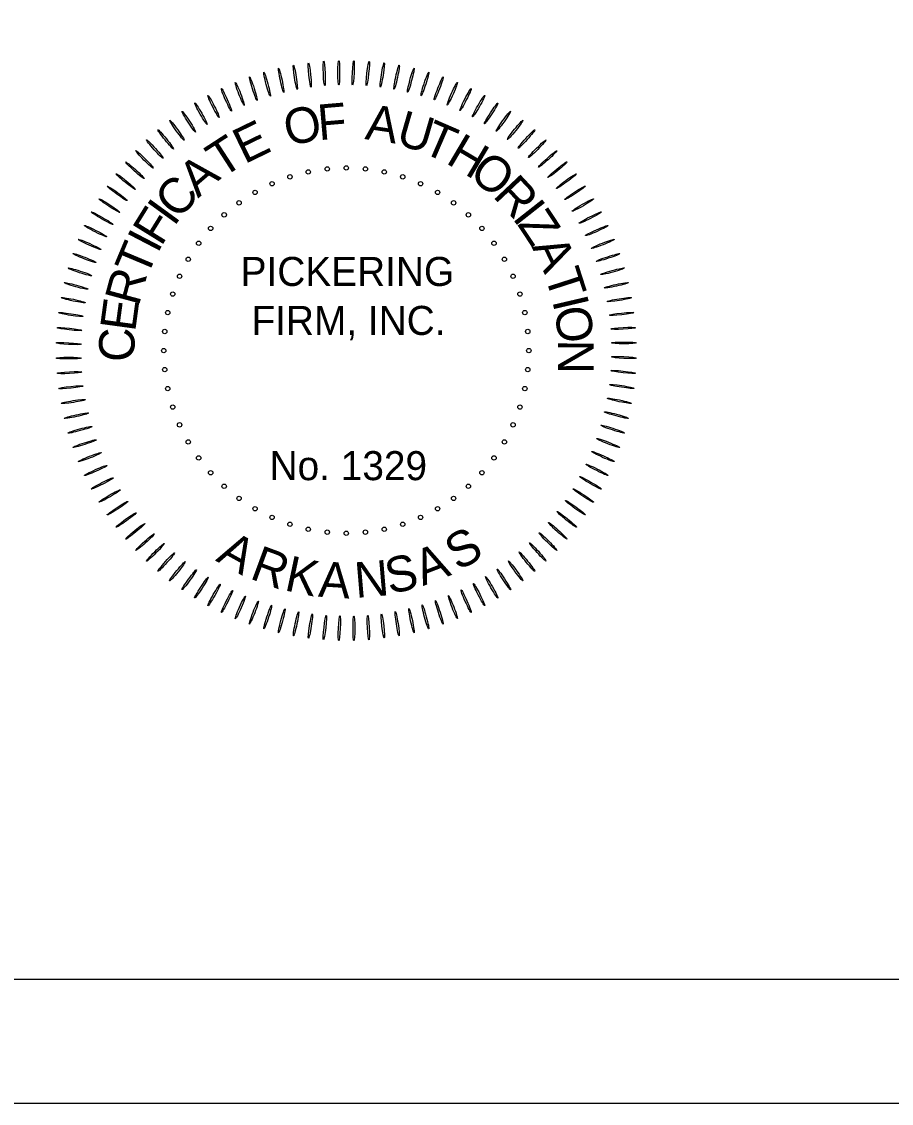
# Model space of a CAD drawing. Extents: x 1368042 to 1371376, y 380392 to 382637.
# Drawn here: x 1370746.8 to 1371026.4, y 380392 to 380739.5 of the extents above; entities that cross this region are included whole.
import ezdxf

# ---------------------------------------------------------------- set-up
doc = ezdxf.new("R2010")
doc.units = 0
for name, color, linetype in [('G-COA-ANNO', 7, 'Continuous'), ('G-COA-LINE', 7, 'Continuous'), ('R_Border', 7, 'Continuous'), ('R_No Plot', 7, 'Continuous'), ('STAMP_COA', 7, 'Continuous')]:
    doc.layers.add(name, color=color, linetype=linetype)

# ---------------------------------------------------------------- blocks, each defined once
blk = doc.blocks.new('Pickering-COA AR-ENG')
at = {"layer": 'G-COA-LINE'}
for centre in [(-0.427, 5.137), (-0.427, 5.137), (-0.228, 5.168), (-0.228, 5.168), (-0.028, 5.179), (-0.028, 5.179), (0.173, 5.168), (0.173, 5.168), (0.371, 5.137), (0.371, 5.137), (-0.808, 5.013), (-0.808, 5.013), (-0.62, 5.085), (-0.62, 5.085), (0.565, 5.085), (0.565, 5.085), (0.752, 5.013), (0.752, 5.013), (-0.987, 4.922), (-0.987, 4.922), (0.931, 4.922), (0.931, 4.922), (-1.155, 4.812), (-1.155, 4.812), (1.099, 4.812), (1.099, 4.812), (-1.311, 4.686), (-1.311, 4.686), (1.255, 4.686), (1.255, 4.686), (-1.453, 4.544), (-1.453, 4.544), (1.397, 4.544), (1.397, 4.544), (-1.579, 4.388), (-1.579, 4.388), (1.524, 4.388), (1.524, 4.388), (-1.689, 4.22), (-1.689, 4.22), (1.633, 4.22), (1.633, 4.22), (-1.78, 4.041), (-1.78, 4.041), (1.724, 4.041), (1.724, 4.041), (-1.852, 3.854), (-1.852, 3.854), (1.796, 3.854), (1.796, 3.854), (-1.904, 3.66), (-1.904, 3.66), (1.848, 3.66), (1.848, 3.66), (-1.935, 3.461), (-1.935, 3.461), (1.879, 3.461), (1.879, 3.461), (-1.946, 3.261), (-1.946, 3.261), (1.89, 3.261), (1.89, 3.261), (-1.935, 3.061), (-1.935, 3.061), (1.879, 3.061), (1.879, 3.061), (-1.904, 2.862), (-1.904, 2.862), (1.848, 2.862), (1.848, 2.862), (-1.852, 2.668), (-1.852, 2.668), (1.796, 2.668), (1.796, 2.668), (-1.78, 2.481), (-1.78, 2.481), (1.724, 2.481), (1.724, 2.481), (-1.689, 2.302), (-1.689, 2.302), (1.633, 2.302), (1.633, 2.302), (-1.579, 2.134), (-1.579, 2.134), (1.524, 2.134), (1.524, 2.134), (-1.453, 1.978), (-1.453, 1.978), (1.397, 1.978), (1.397, 1.978), (-1.311, 1.836), (-1.311, 1.836), (1.255, 1.836), (1.255, 1.836), (-1.155, 1.709), (-1.155, 1.709), (1.099, 1.709), (1.099, 1.709), (-0.987, 1.6), (-0.987, 1.6), (0.931, 1.6), (0.931, 1.6), (-0.808, 1.509), (-0.808, 1.509), (0.752, 1.509), (0.752, 1.509), (-0.62, 1.437), (-0.62, 1.437), (-0.427, 1.385), (-0.427, 1.385), (-0.228, 1.354), (-0.228, 1.354), (-0.028, 1.343), (-0.028, 1.343), (0.173, 1.354), (0.173, 1.354), (0.371, 1.385), (0.371, 1.385), (0.565, 1.437), (0.565, 1.437)]:
    blk.add_circle(centre, 0.0229, dxfattribs=at)
for centre, major_axis in [((-0.563, 6.13), (0.02, -0.128)), ((-0.563, 6.13), (0.02, -0.128)), ((-0.412, 6.154), (0.014, -0.129)), ((-0.412, 6.154), (0.014, -0.129)), ((-0.26, 6.17), (0.006, -0.13)), ((-0.26, 6.17), (0.006, -0.13)), ((-0.107, 6.178), (0, -0.13)), ((-0.107, 6.178), (0, -0.13)), ((0.045, 6.178), (-0.007, -0.13)), ((0.045, 6.178), (-0.007, -0.13)), ((0.198, 6.171), (-0.014, -0.129)), ((0.198, 6.171), (-0.014, -0.129)), ((0.35, 6.155), (-0.02, -0.128)), ((0.35, 6.155), (-0.02, -0.128)), ((0.501, 6.131), (-0.027, -0.127)), ((0.501, 6.131), (-0.027, -0.127)), ((-1.005, 6.011), (0.04, -0.124)), ((-1.005, 6.011), (0.04, -0.124)), ((-0.86, 6.058), (0.034, -0.126)), ((-0.86, 6.058), (0.034, -0.126)), ((-0.712, 6.098), (0.027, -0.127)), ((-0.712, 6.098), (0.027, -0.127)), ((0.65, 6.099), (-0.034, -0.126)), ((0.65, 6.099), (-0.034, -0.126)), ((0.798, 6.06), (-0.04, -0.124)), ((0.798, 6.06), (-0.04, -0.124)), ((0.943, 6.013), (-0.047, -0.121)), ((0.943, 6.013), (-0.047, -0.121)), ((-1.147, 5.956), (0.047, -0.121)), ((-1.147, 5.956), (0.047, -0.121)), ((1.086, 5.958), (-0.053, -0.119)), ((1.086, 5.958), (-0.053, -0.119)), ((-1.423, 5.824), (0.059, -0.116)), ((-1.423, 5.824), (0.059, -0.116)), ((-1.287, 5.894), (0.053, -0.119)), ((-1.287, 5.894), (0.053, -0.119)), ((1.225, 5.896), (-0.059, -0.116)), ((1.225, 5.896), (-0.059, -0.116)), ((1.362, 5.827), (-0.065, -0.113)), ((1.362, 5.827), (-0.065, -0.113)), ((-1.555, 5.748), (0.065, -0.113)), ((-1.555, 5.748), (0.065, -0.113)), ((1.494, 5.751), (-0.071, -0.109)), ((1.494, 5.751), (-0.071, -0.109)), ((-1.807, 5.574), (0.076, -0.105)), ((-1.807, 5.574), (0.076, -0.105)), ((-1.683, 5.664), (0.071, -0.109)), ((-1.683, 5.664), (0.071, -0.109)), ((1.622, 5.668), (-0.076, -0.105)), ((1.622, 5.668), (-0.076, -0.105)), ((1.746, 5.578), (-0.082, -0.101)), ((1.746, 5.578), (-0.082, -0.101)), ((-1.925, 5.478), (0.082, -0.101)), ((-1.925, 5.478), (0.082, -0.101)), ((1.865, 5.482), (-0.087, -0.0967)), ((1.865, 5.482), (-0.087, -0.0967)), ((-2.039, 5.376), (0.087, -0.0967)), ((-2.039, 5.376), (0.087, -0.0967)), ((1.978, 5.38), (-0.092, -0.092)), ((1.978, 5.38), (-0.092, -0.092)), ((-2.147, 5.268), (0.092, -0.092)), ((-2.147, 5.268), (0.092, -0.092)), ((2.087, 5.272), (-0.0967, -0.087)), ((2.087, 5.272), (-0.0967, -0.087)), ((-2.249, 5.154), (0.0967, -0.087)), ((-2.249, 5.154), (0.0967, -0.087)), ((2.189, 5.159), (-0.101, -0.082)), ((2.189, 5.159), (-0.101, -0.082)), ((-2.345, 5.035), (0.101, -0.082)), ((-2.345, 5.035), (0.101, -0.082)), ((2.285, 5.04), (-0.105, -0.076)), ((2.285, 5.04), (-0.105, -0.076)), ((-2.434, 4.911), (0.105, -0.076)), ((-2.434, 4.911), (0.105, -0.076)), ((2.375, 4.917), (-0.109, -0.071)), ((2.375, 4.917), (-0.109, -0.071)), ((-2.517, 4.783), (0.109, -0.071)), ((-2.517, 4.783), (0.109, -0.071)), ((2.458, 4.789), (-0.113, -0.065)), ((2.458, 4.789), (-0.113, -0.065)), ((-2.594, 4.651), (0.113, -0.065)), ((-2.594, 4.651), (0.113, -0.065)), ((2.535, 4.657), (-0.116, -0.059)), ((2.535, 4.657), (-0.116, -0.059)), ((-2.663, 4.515), (0.116, -0.059)), ((-2.663, 4.515), (0.116, -0.059)), ((2.604, 4.521), (-0.119, -0.053)), ((2.604, 4.521), (-0.119, -0.053)), ((-2.725, 4.375), (0.119, -0.053)), ((-2.725, 4.375), (0.119, -0.053)), ((2.667, 4.381), (-0.121, -0.047)), ((2.667, 4.381), (-0.121, -0.047)), ((-2.779, 4.232), (0.121, -0.047)), ((-2.779, 4.232), (0.121, -0.047)), ((2.722, 4.238), (-0.124, -0.04)), ((2.722, 4.238), (-0.124, -0.04)), ((-2.827, 4.087), (0.124, -0.04)), ((-2.827, 4.087), (0.124, -0.04)), ((2.769, 4.093), (-0.126, -0.034)), ((2.769, 4.093), (-0.126, -0.034)), ((-2.866, 3.939), (0.126, -0.034)), ((-2.866, 3.939), (0.126, -0.034)), ((2.809, 3.946), (-0.127, -0.027)), ((2.809, 3.946), (-0.127, -0.027)), ((-2.897, 3.79), (0.127, -0.027)), ((-2.897, 3.79), (0.127, -0.027)), ((2.841, 3.796), (-0.128, -0.02)), ((2.841, 3.796), (-0.128, -0.02)), ((-2.921, 3.639), (0.128, -0.02)), ((-2.921, 3.639), (0.128, -0.02)), ((2.865, 3.646), (-0.129, -0.013)), ((2.865, 3.646), (-0.129, -0.013)), ((-2.937, 3.487), (0.129, -0.014)), ((-2.937, 3.487), (0.129, -0.014)), ((2.881, 3.494), (-0.13, -0.007)), ((2.881, 3.494), (-0.13, -0.007)), ((-2.945, 3.334), (0.13, -0.007)), ((-2.945, 3.334), (0.13, -0.007)), ((2.889, 3.341), (-0.13, 0)), ((2.889, 3.341), (-0.13, 0)), ((-2.945, 3.182), (0.13, 0)), ((-2.945, 3.182), (0.13, 0)), ((2.889, 3.188), (-0.13, 0.006)), ((2.889, 3.188), (-0.13, 0.006)), ((-2.936, 3.029), (0.13, 0.007)), ((-2.936, 3.029), (0.13, 0.007)), ((2.881, 3.036), (-0.129, 0.014)), ((2.881, 3.036), (-0.129, 0.014)), ((-2.92, 2.876), (0.129, 0.013)), ((-2.92, 2.876), (0.129, 0.013)), ((2.866, 2.884), (-0.128, 0.02)), ((2.866, 2.884), (-0.128, 0.02)), ((-2.896, 2.726), (0.128, 0.02)), ((-2.896, 2.726), (0.128, 0.02)), ((2.842, 2.733), (-0.127, 0.027)), ((2.842, 2.733), (-0.127, 0.027)), ((2.81, 2.583), (-0.126, 0.034)), ((2.81, 2.583), (-0.126, 0.034)), ((-2.864, 2.577), (0.127, 0.027)), ((-2.864, 2.577), (0.127, 0.027)), ((-2.825, 2.429), (0.126, 0.034)), ((-2.825, 2.429), (0.126, 0.034)), ((2.771, 2.436), (-0.124, 0.04)), ((2.771, 2.436), (-0.124, 0.04)), ((-2.777, 2.284), (0.124, 0.04)), ((-2.777, 2.284), (0.124, 0.04)), ((2.724, 2.29), (-0.121, 0.047)), ((2.724, 2.29), (-0.121, 0.047)), ((-2.722, 2.142), (0.121, 0.047)), ((-2.722, 2.142), (0.121, 0.047)), ((2.669, 2.148), (-0.119, 0.053)), ((2.669, 2.148), (-0.119, 0.053)), ((-2.66, 2.002), (0.119, 0.053)), ((-2.66, 2.002), (0.119, 0.053)), ((2.607, 2.008), (-0.116, 0.059)), ((2.607, 2.008), (-0.116, 0.059)), ((2.538, 1.872), (-0.113, 0.065)), ((2.538, 1.872), (-0.113, 0.065)), ((-2.591, 1.866), (0.116, 0.059)), ((-2.591, 1.866), (0.116, 0.059)), ((-2.514, 1.734), (0.113, 0.065)), ((-2.514, 1.734), (0.113, 0.065)), ((2.462, 1.739), (-0.109, 0.071)), ((2.462, 1.739), (-0.109, 0.071)), ((-2.431, 1.606), (0.109, 0.071)), ((-2.431, 1.606), (0.109, 0.071)), ((2.379, 1.611), (-0.105, 0.076)), ((2.379, 1.611), (-0.105, 0.076)), ((-2.341, 1.482), (0.105, 0.076)), ((-2.341, 1.482), (0.105, 0.076)), ((2.289, 1.488), (-0.101, 0.082)), ((2.289, 1.488), (-0.101, 0.082)), ((-2.244, 1.364), (0.101, 0.082)), ((-2.244, 1.364), (0.101, 0.082)), ((2.193, 1.369), (-0.0967, 0.087)), ((2.193, 1.369), (-0.0967, 0.087)), ((-2.142, 1.25), (0.0967, 0.087)), ((-2.142, 1.25), (0.0967, 0.087)), ((2.091, 1.255), (-0.092, 0.092)), ((2.091, 1.255), (-0.092, 0.092)), ((-2.034, 1.142), (0.092, 0.092)), ((-2.034, 1.142), (0.092, 0.092)), ((-1.92, 1.04), (0.087, 0.0967)), ((-1.92, 1.04), (0.087, 0.0967)), ((1.87, 1.045), (-0.082, 0.101)), ((1.87, 1.045), (-0.082, 0.101)), ((1.983, 1.147), (-0.087, 0.0967)), ((1.983, 1.147), (-0.087, 0.0967)), ((-1.802, 0.944), (0.082, 0.101)), ((-1.802, 0.944), (0.082, 0.101)), ((1.751, 0.948), (-0.076, 0.105)), ((1.751, 0.948), (-0.076, 0.105)), ((-1.678, 0.855), (0.076, 0.105)), ((-1.678, 0.855), (0.076, 0.105)), ((1.628, 0.858), (-0.071, 0.109)), ((1.628, 0.858), (-0.071, 0.109)), ((-1.55, 0.772), (0.071, 0.109)), ((-1.55, 0.772), (0.071, 0.109)), ((-1.417, 0.695), (0.065, 0.113)), ((-1.417, 0.695), (0.065, 0.113)), ((1.367, 0.699), (-0.059, 0.116)), ((1.367, 0.699), (-0.059, 0.116)), ((1.5, 0.775), (-0.065, 0.113)), ((1.5, 0.775), (-0.065, 0.113)), ((-1.281, 0.626), (0.059, 0.116)), ((-1.281, 0.626), (0.059, 0.116)), ((-1.141, 0.564), (0.053, 0.119)), ((-1.141, 0.564), (0.053, 0.119)), ((1.092, 0.567), (-0.047, 0.121)), ((1.092, 0.567), (-0.047, 0.121)), ((1.231, 0.629), (-0.053, 0.119)), ((1.231, 0.629), (-0.053, 0.119)), ((-0.999, 0.51), (0.047, 0.121)), ((-0.999, 0.51), (0.047, 0.121)), ((-0.853, 0.463), (0.04, 0.124)), ((-0.853, 0.463), (0.04, 0.124)), ((0.804, 0.464), (-0.034, 0.126)), ((0.804, 0.464), (-0.034, 0.126)), ((0.949, 0.512), (-0.04, 0.124)), ((0.949, 0.512), (-0.04, 0.124)), ((-0.706, 0.423), (0.034, 0.126)), ((-0.706, 0.423), (0.034, 0.126)), ((-0.556, 0.392), (0.027, 0.127)), ((-0.556, 0.392), (0.027, 0.127)), ((-0.405, 0.368), (0.02, 0.128)), ((-0.405, 0.368), (0.02, 0.128)), ((-0.253, 0.352), (0.014, 0.129)), ((-0.253, 0.352), (0.014, 0.129)), ((-0.101, 0.344), (0.007, 0.13)), ((-0.101, 0.344), (0.007, 0.13)), ((0.052, 0.344), (0, 0.13)), ((0.052, 0.344), (0, 0.13)), ((0.204, 0.353), (-0.007, 0.13)), ((0.204, 0.353), (-0.007, 0.13)), ((0.356, 0.369), (-0.014, 0.129)), ((0.356, 0.369), (-0.014, 0.129)), ((0.507, 0.393), (-0.02, 0.128)), ((0.507, 0.393), (-0.02, 0.128)), ((0.657, 0.425), (-0.027, 0.127)), ((0.657, 0.425), (-0.027, 0.127))]:
    blk.add_ellipse(centre, major_axis=major_axis, ratio=0.070301, dxfattribs=at)
at = {"layer": 'G-COA-ANNO'}
for s, rotation, p in [('O', 12.2619, (-0.64, 5.405)), ('F', 4.8299, (-0.315, 5.469)), ('A', 351.5891, (0.16, 5.482)), ('E', 25.8553, (-1.098, 5.215)), ('U', 343.8069, (0.48, 5.43)), ('T', 336.5727, (0.748, 5.349)), ('T', 32.9353, (-1.337, 5.064)), ('H', 329.3464, (1.006, 5.235)), ('A', 40.7411, (-1.586, 4.856)), ('O', 321.4937, (1.246, 5.091)), ('C', 48.8967, (-1.791, 4.624)), ('R', 313.2703, (1.502, 4.882)), ('F', 58.2456, (-1.973, 4.346)), ('I', 53.972, (-1.839, 4.554)), ('I', 308.2054, (1.708, 4.653)), ('Z', 303.4877, (1.763, 4.587)), ('I', 62.5192, (-2.011, 4.27)), ('T', 67.2448, (-2.125, 4.013)), ('A', 295.6897, (1.917, 4.351)), ('R', 74.8418, (-2.21, 3.716)), ('T', 287.884, (2.053, 4.057)), ('E', 82.2613, (-2.247, 3.45)), ('I', 283.1584, (2.134, 3.787)), ('O', 277.8065, (2.157, 3.704)), ('C', 89.6911, (-2.253, 3.141)), ('N', 269.9408, (2.197, 3.376)), ('S', 29.451, (1.146, 0.941)), ('A', 331.0076, (-1.409, 1.057)), ('R', 339.6665, (-1.054, 0.871)), ('A', 21.072, (0.776, 0.787)), ('K', 347.9673, (-0.69, 0.746)), ('A', 356.4471, (-0.328, 0.677)), ('N', 4.7993, (0.073, 0.663)), ('S', 12.6929, (0.427, 0.701))]:
    blk.add_text(s, height=0.373, rotation=rotation, dxfattribs=at).set_placement(p)
for s, p in [('PICKERING', (-1.138, 3.939)), ('FIRM, INC.', (-1.024, 3.425)), ('No. 1329', (-0.834, 1.9))]:
    blk.add_text(s, height=0.3049, dxfattribs=at).set_placement(p)

msp = doc.modelspace()

# ---------------------------------------------------------------- linework, layer by layer
at = {"layer": 'R_Border'}
msp.add_line((1371328.04, 380431.81), (1368166.24, 380431.81), dxfattribs=at)
at = {"layer": 'R_No Plot'}
msp.add_line((1368042.23, 380392.03), (1371375.57, 380392.03), dxfattribs=at)
msp.add_lwpolyline([(1368042.17, 382525.36), (1371375.57, 382525.36), (1371375.57, 380391.98), (1368042.17, 380391.98)], close=True, dxfattribs=at)

# ---------------------------------------------------------------- block references
at = {"layer": 'STAMP_COA', "xscale": 30.59673509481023, "yscale": 30.596735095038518}
msp.add_blockref('Pickering-COA AR-ENG', (1370851.99, 380534.06), dxfattribs=at)

doc.saveas('drawing.dxf')
